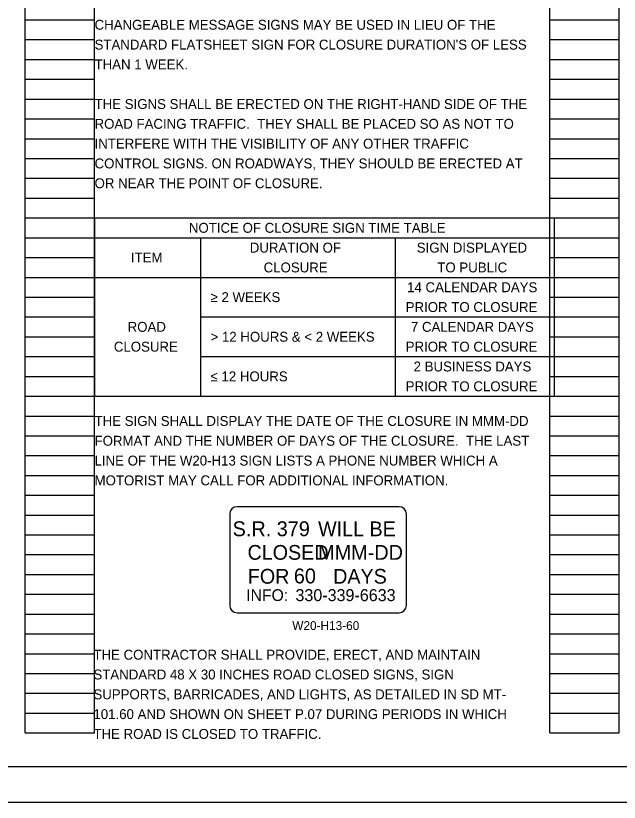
# Model space of a CAD drawing. Extents: x -59.3 to 34, y -1.2 to 22.
# Drawn here: x 16.13 to 24.66, y 0 to 11.12 of the extents above; entities that cross this region are included whole.
import ezdxf

# ---------------------------------------------------------------- set-up
doc = ezdxf.new("R2010")
doc.units = 0
for name, color, linetype in [('RD_P_Text', 7, 'Continuous'), ('SH_Border', 7, 'Continuous'), ('SH_Cut_Line', 7, 'Continuous'), ('SH_Data', 7, 'Continuous'), ('SN_P_Signs', 7, 'Continuous'), ('SN_P_Text', 7, 'Continuous')]:
    doc.layers.add(name, color=color, linetype=linetype)

msp = doc.modelspace()

# ---------------------------------------------------------------- linework, layer by layer
at = {"layer": 'RD_P_Text'}
for p, q in [((16.26, 0.98), (16.26, 21.14)), ((17.24, 0.98), (17.24, 21.14)), ((23.68, 0.98), (23.68, 21.14)), ((24.66, 0.98), (24.66, 21.14)), ((16.26, 11.06), (17.24, 11.06)), ((23.68, 11.06), (24.66, 11.06)), ((16.26, 10.78), (17.24, 10.78)), ((23.68, 10.78), (24.66, 10.78)), ((16.26, 10.5), (17.24, 10.5)), ((23.68, 10.5), (24.66, 10.5)), ((16.26, 10.22), (17.24, 10.22)), ((23.68, 10.22), (24.66, 10.22)), ((16.26, 9.94), (17.24, 9.94)), ((23.68, 9.94), (24.66, 9.94)), ((16.26, 9.66), (17.24, 9.66)), ((23.68, 9.66), (24.66, 9.66)), ((16.26, 9.38), (17.24, 9.38)), ((23.68, 9.38), (24.66, 9.38)), ((16.26, 9.1), (17.24, 9.1)), ((23.68, 9.1), (24.66, 9.1)), ((16.26, 8.82), (17.24, 8.82)), ((23.68, 8.82), (24.66, 8.82)), ((16.26, 8.54), (17.24, 8.54)), ((23.68, 8.54), (24.66, 8.54)), ((16.26, 8.26), (17.24, 8.26)), ((17.24, 8.26), (17.24, 5.74)), ((17.24, 8.26), (23.74, 8.26)), ((23.68, 8.26), (24.66, 8.26)), ((23.74, 8.26), (23.74, 5.74)), ((16.26, 7.98), (17.24, 7.98)), ((17.24, 7.98), (23.74, 7.98)), ((18.74, 7.98), (18.74, 5.74)), ((21.49, 7.98), (21.49, 5.74)), ((23.68, 7.98), (24.66, 7.98)), ((16.26, 7.7), (17.24, 7.7)), ((23.68, 7.7), (24.66, 7.7)), ((16.26, 7.42), (17.24, 7.42)), ((17.24, 7.42), (23.74, 7.42)), ((23.68, 7.42), (24.66, 7.42)), ((16.26, 7.14), (17.24, 7.14)), ((23.68, 7.14), (24.66, 7.14)), ((16.26, 6.86), (17.24, 6.86)), ((18.74, 6.86), (23.74, 6.86)), ((23.68, 6.86), (24.66, 6.86)), ((16.26, 6.58), (17.24, 6.58)), ((23.68, 6.58), (24.66, 6.58)), ((16.26, 6.3), (17.24, 6.3)), ((18.74, 6.3), (23.74, 6.3)), ((23.68, 6.3), (24.66, 6.3)), ((16.26, 6.02), (17.24, 6.02)), ((23.68, 6.02), (24.66, 6.02)), ((16.26, 5.74), (17.24, 5.74)), ((17.24, 5.74), (23.74, 5.74)), ((23.68, 5.74), (24.66, 5.74)), ((16.26, 5.46), (17.24, 5.46)), ((23.68, 5.46), (24.66, 5.46)), ((16.26, 5.18), (17.24, 5.18)), ((23.68, 5.18), (24.66, 5.18)), ((16.26, 4.9), (17.24, 4.9)), ((23.68, 4.9), (24.66, 4.9)), ((16.26, 4.62), (17.24, 4.62)), ((23.68, 4.62), (24.66, 4.62)), ((16.26, 4.34), (17.24, 4.34)), ((23.68, 4.34), (24.66, 4.34)), ((16.26, 4.06), (17.24, 4.06)), ((23.68, 4.06), (24.66, 4.06)), ((16.26, 3.78), (17.24, 3.78)), ((23.68, 3.78), (24.66, 3.78)), ((16.26, 3.5), (17.24, 3.5)), ((23.68, 3.5), (24.66, 3.5)), ((16.26, 3.22), (17.24, 3.22)), ((23.68, 3.22), (24.66, 3.22)), ((16.26, 2.94), (17.24, 2.94)), ((23.68, 2.94), (24.66, 2.94)), ((16.26, 2.66), (17.24, 2.66)), ((23.68, 2.66), (24.66, 2.66)), ((16.26, 2.38), (17.24, 2.38)), ((23.68, 2.38), (24.66, 2.38)), ((16.26, 2.1), (17.24, 2.1)), ((23.68, 2.1), (24.66, 2.1)), ((16.26, 1.82), (17.24, 1.82)), ((23.68, 1.82), (24.66, 1.82)), ((16.26, 1.54), (17.24, 1.54)), ((23.68, 1.54), (24.66, 1.54)), ((16.26, 1.26), (17.24, 1.26)), ((23.68, 1.26), (24.66, 1.26)), ((16.26, 0.98), (17.24, 0.98)), ((23.68, 0.98), (24.66, 0.98))]:
    msp.add_line(p, q, dxfattribs=at)
at = {"layer": 'SH_Border'}
msp.add_lwpolyline([(1.5, 21.5), (33.5, 21.5), (33.5, 0.5), (1.5, 0.5)], close=True, dxfattribs=at)
at = {"layer": 'SH_Cut_Line'}
msp.add_lwpolyline([(0, 0), (34, 0), (34, 22), (0, 22)], close=True, dxfattribs=at)
at = {"layer": 'SN_P_Signs'}
for p, q in [((21.547, 4.178), (19.255, 4.178)), ((19.151, 4.074), (19.151, 2.782)), ((21.651, 2.782), (21.651, 4.074)), ((19.255, 2.678), (21.547, 2.678))]:
    msp.add_line(p, q, dxfattribs=at)
for centre, start, end in [((19.255, 4.074), 90, 180), ((21.547, 4.074), 0, 90), ((19.255, 2.782), 180, 270), ((21.547, 2.782), 270, 360)]:
    msp.add_arc(centre, 0.104, start, end, dxfattribs=at)

# ---------------------------------------------------------------- texts
at = {"layer": 'RD_P_Text'}
for s, p in [('NOTICE OF CLOSURE SIGN TIME TABLE', (18.574, 8.05)), ('DURATION OF', (19.435, 7.77)), ('SIGN DISPLAYED', (21.796, 7.77)), ('ITEM', (17.754, 7.63)), ('CLOSURE', (19.631, 7.49)), ('TO PUBLIC', (22.087, 7.49)), ('ROAD', (17.708, 6.65)), ('CLOSURE', (17.513, 6.37))]:
    msp.add_text(s, height=0.14, dxfattribs=at).set_placement(p)
at = {"layer": 'SH_Data'}
for s, height, p in [('CHANGEABLE MESSAGE SIGNS MAY BE USED IN LIEU OF THE ', 0.14, (17.24, 10.92)), ("STANDARD FLATSHEET SIGN FOR CLOSURE DURATION'S OF LESS ", 0.14, (17.24, 10.64)), ('THAN 1 WEEK. ', 0.14, (17.24, 10.36)), ('THE SIGNS SHALL BE ERECTED ON THE RIGHT-HAND SIDE OF THE ', 0.14, (17.24, 9.8)), ('ROAD FACING TRAFFIC.  THEY SHALL BE PLACED SO AS NOT TO ', 0.14, (17.24, 9.52)), ('INTERFERE WITH THE VISIBILITY OF ANY OTHER TRAFFIC ', 0.14, (17.24, 9.24)), ('CONTROL SIGNS. ON ROADWAYS, THEY SHOULD BE ERECTED AT ', 0.14, (17.24, 8.96)), ('OR NEAR THE POINT OF CLOSURE.', 0.14, (17.24, 8.68)), ('14 CALENDAR DAYS', 0.14, (21.66, 7.21)), ('≥ 2 WEEKS', 0.14, (18.88, 7.07)), ('PRIOR TO CLOSURE', 0.14, (21.64, 6.93)), ('7 CALENDAR DAYS', 0.14, (21.714, 6.65)), ('> 12 HOURS & < 2 WEEKS', 0.14, (18.88, 6.51)), ('PRIOR TO CLOSURE', 0.14, (21.64, 6.37)), ('2 BUSINESS DAYS', 0.14, (21.752, 6.09)), ('≤ 12 HOURS', 0.14, (18.88, 5.95)), ('PRIOR TO CLOSURE', 0.14, (21.64, 5.81)), ('THE SIGN SHALL DISPLAY THE DATE OF THE CLOSURE IN MMM-DD ', 0.14, (17.24, 5.32)), ('FORMAT AND THE NUMBER OF DAYS OF THE CLOSURE.  THE LAST ', 0.14, (17.24, 5.04)), ('LINE OF THE W20-H13 SIGN LISTS A PHONE NUMBER WHICH A ', 0.14, (17.24, 4.76)), ('MOTORIST MAY CALL FOR ADDITIONAL INFORMATION.', 0.14, (17.24, 4.48)), ('S.R. 379', 0.21, (19.192, 3.761)), ('MMM-DD', 0.21, (20.401, 3.427)), ('60', 0.21, (20.058, 3.094)), ('330-339-6633', 0.17, (20.081, 2.843)), ('THE CONTRACTOR SHALL PROVIDE, ERECT, AND MAINTAIN ', 0.14, (17.224, 2.016)), ('STANDARD 48 X 30 INCHES ROAD CLOSED SIGNS, SIGN ', 0.14, (17.224, 1.736)), ('SUPPORTS, BARRICADES, AND LIGHTS, AS DETAILED IN SD MT-', 0.14, (17.224, 1.456)), ('101.60 AND SHOWN ON SHEET P.07 DURING PERIODS IN WHICH ', 0.14, (17.224, 1.176)), ('THE ROAD IS CLOSED TO TRAFFIC. ', 0.14, (17.224, 0.896))]:
    msp.add_text(s, height=height, dxfattribs=at).set_placement(p)
at = {"layer": 'SN_P_Signs'}
for s, height, p in [('WILL BE', 0.2083, (20.401, 3.761)), ('CLOSED', 0.2083, (19.403, 3.428)), ('FOR        DAYS', 0.20833, (19.407, 3.09)), ('INFO:', 0.1666, (19.384, 2.845))]:
    msp.add_text(s, height=height, dxfattribs=at).set_placement(p)
at = {"layer": 'SN_P_Text'}
msp.add_text('W20-H13-60', height=0.125, dxfattribs=at).set_placement((20.036, 2.435))

doc.saveas('drawing.dxf')
